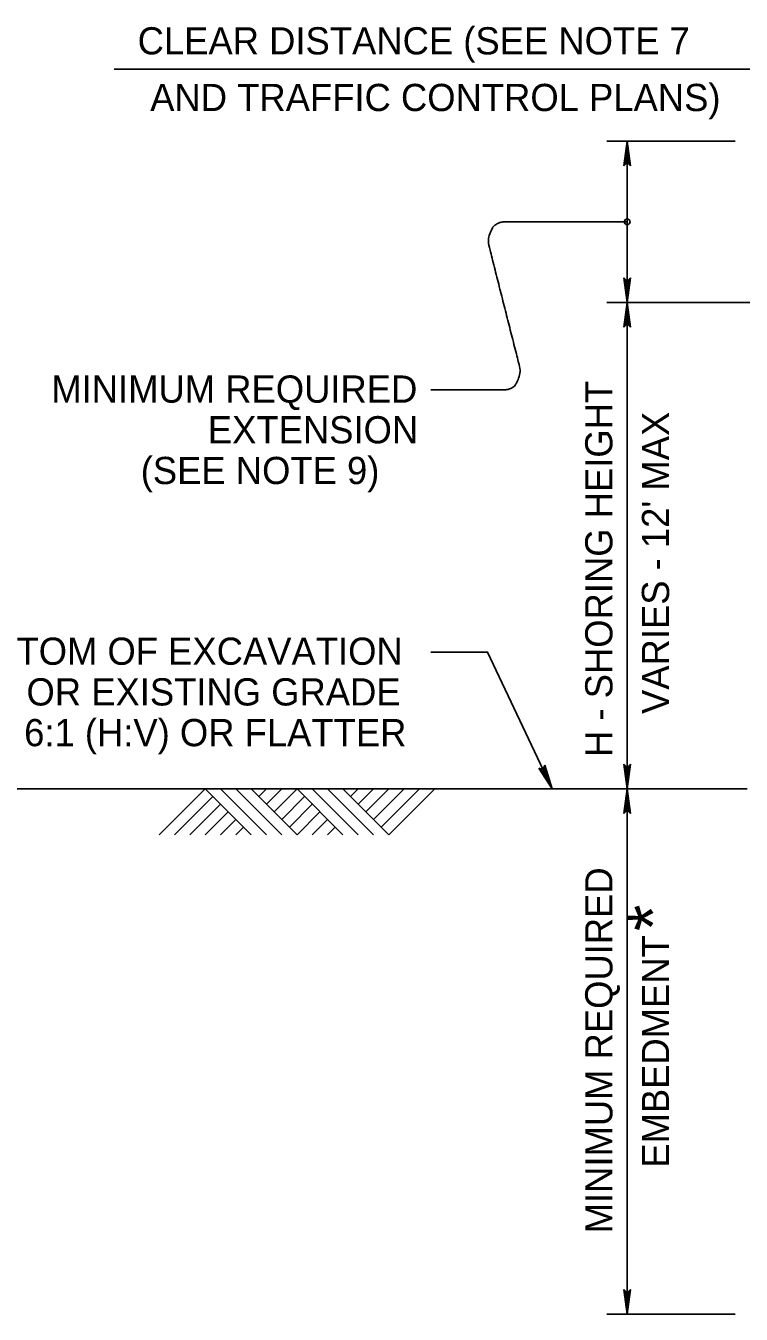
# Model space of a CAD drawing. Extents: x 1252282 to 1252638, y 733735 to 733845.
# Drawn here: x 1252490.12 to 1252507.94, y 733756.38 to 733788.47 of the extents above; entities that cross this region are included whole.
import ezdxf

# ---------------------------------------------------------------- set-up
doc = ezdxf.new("R2010")
doc.units = 0
doc.layers.add('Default', color=7, linetype='Continuous')

msp = doc.modelspace()

# ---------------------------------------------------------------- linework, layer by layer
at = {"layer": 'Default'}
for p, q in [((1252511.812, 733787.388), (1252492.328, 733787.388)), ((1252507.788, 733785.595), (1252504.594, 733785.595)), ((1252505.1, 733785.595), (1252505.017, 733784.983)), ((1252505.028, 733784.994), (1252505.1, 733785.595)), ((1252505.1, 733785.595), (1252505.04, 733785.006)), ((1252505.052, 733785.017), (1252505.1, 733785.595)), ((1252505.1, 733785.595), (1252505.065, 733785.028)), ((1252505.076, 733785.039), (1252505.1, 733785.595)), ((1252505.1, 733785.595), (1252505.088, 733785.051)), ((1252505.1, 733785.595), (1252505.182, 733784.983)), ((1252505.1, 733785.062), (1252505.1, 733785.595)), ((1252505.111, 733785.051), (1252505.1, 733785.595)), ((1252505.1, 733785.595), (1252505.123, 733785.039)), ((1252505.135, 733785.028), (1252505.1, 733785.595)), ((1252505.1, 733785.595), (1252505.147, 733785.017)), ((1252505.159, 733785.006), (1252505.1, 733785.595)), ((1252505.1, 733785.595), (1252505.17, 733784.994)), ((1252505.1, 733756.376), (1252505.1, 733785.595)), ((1252505.017, 733784.983), (1252505.1, 733785.062)), ((1252505.1, 733785.062), (1252505.182, 733784.983)), ((1252505.1, 733781.576), (1252505.018, 733782.189)), ((1252505.1, 733782.11), (1252505.018, 733782.189)), ((1252505.1, 733781.576), (1252505.029, 733782.178)), ((1252505.04, 733782.166), (1252505.1, 733781.576)), ((1252505.1, 733781.576), (1252505.052, 733782.155)), ((1252505.065, 733782.143), (1252505.1, 733781.576)), ((1252505.1, 733781.576), (1252505.077, 733782.133)), ((1252505.1, 733781.576), (1252505.183, 733782.189)), ((1252505.183, 733782.189), (1252505.1, 733782.11)), ((1252505.171, 733782.178), (1252505.1, 733781.576)), ((1252505.1, 733781.576), (1252505.159, 733782.166)), ((1252505.147, 733782.155), (1252505.1, 733781.576)), ((1252505.1, 733781.576), (1252505.135, 733782.143)), ((1252505.124, 733782.133), (1252505.1, 733781.576)), ((1252505.088, 733782.121), (1252505.1, 733781.576)), ((1252505.1, 733781.576), (1252505.112, 733782.121)), ((1252505.1, 733782.11), (1252505.1, 733781.576)), ((1252508.496, 733781.576), (1252504.594, 733781.576)), ((1252505.1, 733781.576), (1252505.017, 733780.964)), ((1252505.028, 733780.975), (1252505.1, 733781.576)), ((1252505.1, 733781.576), (1252505.04, 733780.987)), ((1252505.052, 733780.998), (1252505.1, 733781.576)), ((1252505.1, 733781.576), (1252505.065, 733781.01)), ((1252505.076, 733781.02), (1252505.1, 733781.576)), ((1252505.1, 733781.576), (1252505.088, 733781.032)), ((1252505.1, 733781.576), (1252505.182, 733780.964)), ((1252505.1, 733781.043), (1252505.1, 733781.576)), ((1252505.111, 733781.032), (1252505.1, 733781.576)), ((1252505.1, 733781.576), (1252505.123, 733781.02)), ((1252505.135, 733781.01), (1252505.1, 733781.576)), ((1252505.1, 733781.576), (1252505.147, 733780.998)), ((1252505.159, 733780.987), (1252505.1, 733781.576)), ((1252505.1, 733781.576), (1252505.17, 733780.975)), ((1252505.017, 733780.964), (1252505.1, 733781.043)), ((1252505.1, 733781.043), (1252505.182, 733780.964)), ((1252503.233, 733769.461), (1252502.896, 733769.979)), ((1252503.005, 733769.943), (1252502.896, 733769.979)), ((1252503.233, 733769.461), (1252502.912, 733769.974)), ((1252502.927, 733769.968), (1252503.233, 733769.461)), ((1252503.233, 733769.461), (1252502.942, 733769.963)), ((1252502.959, 733769.958), (1252503.233, 733769.461)), ((1252503.233, 733769.461), (1252502.974, 733769.954)), ((1252502.99, 733769.948), (1252503.233, 733769.461)), ((1252503.046, 733770.05), (1252503.005, 733769.943)), ((1252503.005, 733769.943), (1252503.233, 733769.461)), ((1252503.233, 733769.461), (1252503.011, 733769.958)), ((1252503.016, 733769.974), (1252503.233, 733769.461)), ((1252503.233, 733769.461), (1252503.022, 733769.988)), ((1252503.028, 733770.004), (1252503.233, 733769.461)), ((1252503.233, 733769.461), (1252503.034, 733770.019)), ((1252503.04, 733770.035), (1252503.233, 733769.461)), ((1252503.233, 733769.461), (1252503.046, 733770.05)), ((1252505.1, 733769.461), (1252505.018, 733770.073)), ((1252505.1, 733769.994), (1252505.018, 733770.073)), ((1252505.1, 733769.461), (1252505.029, 733770.062)), ((1252505.04, 733770.05), (1252505.1, 733769.461)), ((1252505.1, 733769.461), (1252505.052, 733770.039)), ((1252505.065, 733770.027), (1252505.1, 733769.461)), ((1252505.1, 733769.461), (1252505.077, 733770.017)), ((1252505.088, 733770.005), (1252505.1, 733769.461)), ((1252505.1, 733769.461), (1252505.183, 733770.073)), ((1252505.183, 733770.073), (1252505.1, 733769.994)), ((1252505.171, 733770.062), (1252505.1, 733769.461)), ((1252505.1, 733769.461), (1252505.159, 733770.05)), ((1252505.147, 733770.039), (1252505.1, 733769.461)), ((1252505.1, 733769.461), (1252505.135, 733770.027)), ((1252505.124, 733770.017), (1252505.1, 733769.461)), ((1252505.1, 733769.461), (1252505.112, 733770.005)), ((1252505.1, 733769.994), (1252505.1, 733769.461)), ((1252488.655, 733769.461), (1252508.092, 733769.461)), ((1252493.446, 733768.317), (1252494.59, 733769.461)), ((1252494.59, 733769.461), (1252495.734, 733768.317)), ((1252494.971, 733769.461), (1252496.115, 733768.317)), ((1252495.353, 733769.461), (1252496.496, 733768.317)), ((1252495.734, 733769.461), (1252496.878, 733768.317)), ((1252495.924, 733769.27), (1252496.115, 733769.461)), ((1252496.115, 733769.079), (1252496.496, 733769.461)), ((1252496.306, 733768.889), (1252496.878, 733769.461)), ((1252496.878, 733769.461), (1252498.021, 733768.317)), ((1252497.259, 733769.461), (1252498.402, 733768.317)), ((1252497.64, 733769.461), (1252498.784, 733768.317)), ((1252498.021, 733769.461), (1252499.165, 733768.317)), ((1252498.212, 733769.27), (1252498.402, 733769.461)), ((1252498.402, 733769.079), (1252498.784, 733769.461)), ((1252498.593, 733768.889), (1252499.165, 733769.461)), ((1252498.783, 733768.698), (1252499.546, 733769.461)), ((1252498.974, 733768.507), (1252499.927, 733769.461)), ((1252499.165, 733768.317), (1252500.309, 733769.461)), ((1252505.1, 733769.461), (1252505.017, 733768.848)), ((1252505.028, 733768.859), (1252505.1, 733769.461)), ((1252505.1, 733769.461), (1252505.04, 733768.871)), ((1252505.052, 733768.882), (1252505.1, 733769.461)), ((1252505.1, 733769.461), (1252505.065, 733768.894)), ((1252505.076, 733768.904), (1252505.1, 733769.461)), ((1252505.1, 733769.461), (1252505.088, 733768.916)), ((1252505.1, 733769.461), (1252505.182, 733768.848)), ((1252505.1, 733768.927), (1252505.1, 733769.461)), ((1252505.111, 733768.916), (1252505.1, 733769.461)), ((1252505.1, 733769.461), (1252505.123, 733768.904)), ((1252505.135, 733768.894), (1252505.1, 733769.461)), ((1252505.1, 733769.461), (1252505.147, 733768.882)), ((1252505.159, 733768.871), (1252505.1, 733769.461)), ((1252505.1, 733769.461), (1252505.17, 733768.859)), ((1252493.828, 733768.317), (1252494.781, 733769.27)), ((1252494.209, 733768.317), (1252494.971, 733769.079)), ((1252496.496, 733768.698), (1252497.068, 733769.27)), ((1252496.687, 733768.507), (1252497.259, 733769.079)), ((1252494.59, 733768.317), (1252495.162, 733768.889)), ((1252494.971, 733768.317), (1252495.353, 733768.698)), ((1252496.878, 733768.317), (1252497.449, 733768.889)), ((1252497.259, 733768.317), (1252497.64, 733768.698)), ((1252505.017, 733768.848), (1252505.1, 733768.927)), ((1252505.1, 733768.927), (1252505.182, 733768.848)), ((1252495.353, 733768.317), (1252495.543, 733768.507)), ((1252497.64, 733768.317), (1252497.831, 733768.507)), ((1252505.1, 733756.376), (1252505.018, 733756.988)), ((1252505.1, 733756.909), (1252505.018, 733756.988)), ((1252505.1, 733756.376), (1252505.029, 733756.977)), ((1252505.04, 733756.965), (1252505.1, 733756.376)), ((1252505.1, 733756.376), (1252505.052, 733756.954)), ((1252505.065, 733756.942), (1252505.1, 733756.376)), ((1252505.1, 733756.376), (1252505.077, 733756.932)), ((1252505.088, 733756.92), (1252505.1, 733756.376)), ((1252505.1, 733756.376), (1252505.183, 733756.988)), ((1252505.183, 733756.988), (1252505.1, 733756.909)), ((1252505.171, 733756.977), (1252505.1, 733756.376)), ((1252505.1, 733756.376), (1252505.159, 733756.965)), ((1252505.147, 733756.954), (1252505.1, 733756.376)), ((1252505.1, 733756.376), (1252505.135, 733756.942)), ((1252505.124, 733756.932), (1252505.1, 733756.376)), ((1252505.1, 733756.376), (1252505.112, 733756.92)), ((1252505.1, 733756.909), (1252505.1, 733756.376)), ((1252507.788, 733756.376), (1252504.594, 733756.376))]:
    msp.add_line(p, q, dxfattribs=at)
msp.add_lwpolyline([(1252503.233, 733769.461), (1252501.622, 733772.868), (1252500.214, 733772.868)], dxfattribs=at)
msp.add_circle((1252505.1, 733783.586), 0.0713, dxfattribs=at)
msp.add_open_spline([(1252505.1, 733783.586), (1252503.445, 733783.586), (1252502.762, 733783.586), (1252502.078, 733783.586), (1252502.057, 733783.586), (1252502.036, 733783.584), (1252502.016, 733783.583), (1252501.997, 733783.581), (1252501.978, 733783.577), (1252501.959, 733783.574), (1252501.925, 733783.567), (1252501.894, 733783.555), (1252501.862, 733783.539), (1252501.805, 733783.508), (1252501.761, 733783.466), (1252501.731, 733783.406), (1252501.655, 733783.25), (1252501.634, 733783.086), (1252501.673, 733782.931), (1252501.794, 733782.451), (1252501.916, 733781.971), (1252502.038, 733781.491), (1252502.159, 733781.011), (1252502.281, 733780.531), (1252502.403, 733780.051), (1252502.442, 733779.897), (1252502.42, 733779.732), (1252502.344, 733779.577), (1252502.315, 733779.516), (1252502.27, 733779.474), (1252502.213, 733779.444), (1252502.181, 733779.427), (1252502.15, 733779.416), (1252502.116, 733779.409), (1252502.097, 733779.405), (1252502.079, 733779.401), (1252502.06, 733779.4), (1252502.039, 733779.398), (1252502.018, 733779.397), (1252501.997, 733779.397), (1252501.403, 733779.397), (1252500.808, 733779.397), (1252500.214, 733779.397)], degree=3, dxfattribs=at)

# ---------------------------------------------------------------- texts
for s, height, p in [('CLEAR DISTANCE (SEE NOTE 7', 0.67788, (1252492.909, 733787.755)), ('AND TRAFFIC CONTROL PLANS)', 0.67788, (1252493.222, 733786.344)), ('MINIMUM REQUIRED', 0.67788, (1252490.76, 733779.081)), ('EXTENSION', 0.6779, (1252494.657, 733778.067)), ('(SEE NOTE 9)', 0.67788, (1252492.986, 733777.053)), ('BOTTOM OF EXCAVATION', 0.67788, (1252488.028, 733772.552)), ('OR EXISTING GRADE', 0.67788, (1252490.141, 733771.538)), ('6:1 (H:V) OR FLATTER', 0.67788, (1252490.083, 733770.524))]:
    msp.add_text(s, height=height, dxfattribs=at).set_placement(p)
for s, height, p in [('H - SHORING HEIGHT', 0.67788, (1252504.733, 733770.256)), ("VARIES - 12' MAX", 0.67788, (1252506.144, 733771.327)), ('MINIMUM REQUIRED', 0.67788, (1252504.733, 733758.392)), ('*', 1.271, (1252506.377, 733765.918)), ('EMBEDMENT', 0.6779, (1252506.144, 733760.025))]:
    msp.add_text(s, height=height, rotation=90, dxfattribs=at).set_placement(p)

doc.saveas('drawing.dxf')
